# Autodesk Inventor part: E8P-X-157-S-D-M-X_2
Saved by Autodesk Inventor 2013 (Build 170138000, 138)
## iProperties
Created: 2012-07
Part Number: E8P-X-157-S-D-M-X_2
Material: Allgemein
Document SubType Name: Modeling
Designer: rYan
Density: 1 g/cm^3
Mass: 1.04278 g
Surface Area: 25.6207 cm^2
Volume: 1.04278 cm^3
Author: rYan
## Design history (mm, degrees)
node "E8P-X-157-S-D-M-X_21"
node "E8P-X-157-S-D-M-X_2"
node "Basis1"
